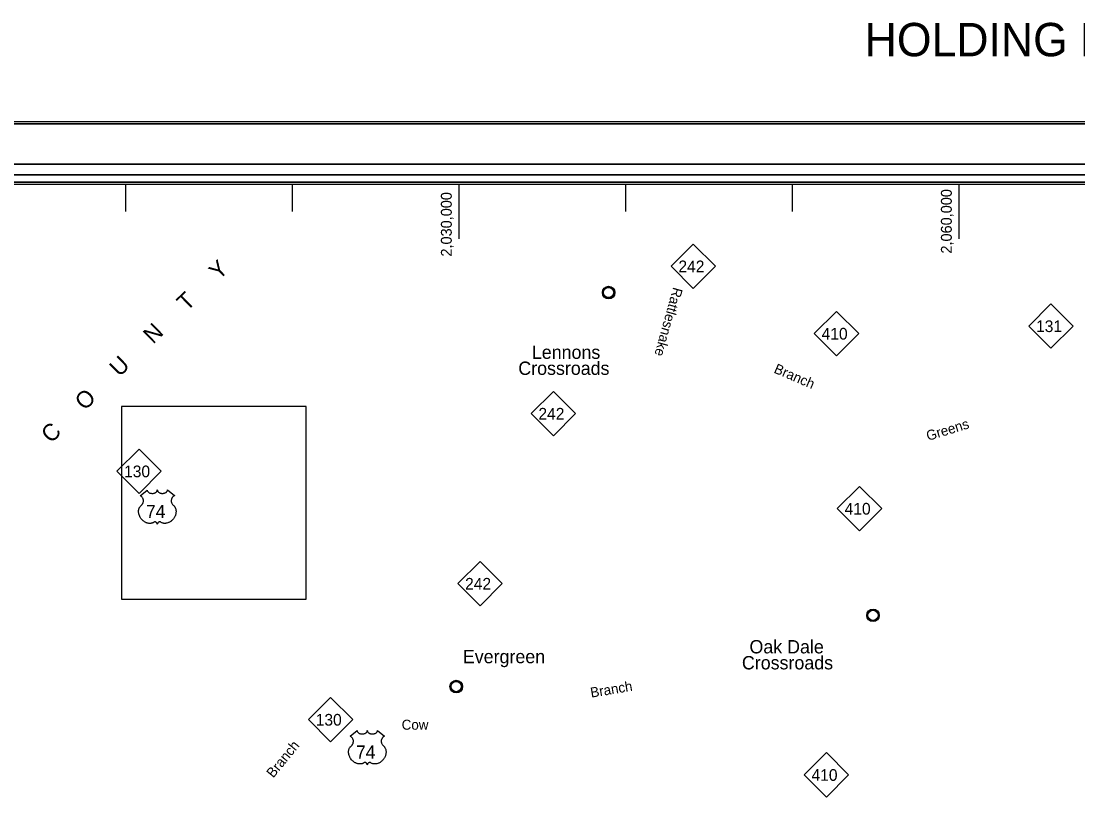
# Model space of a CAD drawing. Extents: x 5197761 to 5514561, y 1890130 to 2080942.
# Drawn here: x 5234499 to 5297901, y 2034063 to 2080942 of the extents above; entities that cross this region are included whole.
import ezdxf

# ---------------------------------------------------------------- set-up
doc = ezdxf.new("R2010")
doc.units = 0
for name, color, linetype in [('Exist Civil Demographics Community CELL', 7, 'Continuous'), ('Exist Civil Demographics Community Label', 7, 'Continuous'), ('Exist Hydrographic Creek Single Shore Label', 7, 'Continuous'), ('Exist Road Primary NC Shield CELL', 7, 'Continuous'), ('Exist Road Primary NC Shield Number Label', 7, 'Continuous'), ('Exist Road Primary US Shield CELL', 7, 'Continuous'), ('Exist Road Primary US Shield Number Label', 7, 'Continuous'), ('Map Preparation Base StatePlane Tick Label', 7, 'Continuous'), ('Map Preparation Base StatePlane Tick Mark', 7, 'Continuous'), ('Map Preparation Border Antique Large Shape', 7, 'Continuous'), ('Map Preparation Border Antique Small Shape', 7, 'Continuous'), ('Map Preparation Border Black Inside Shape', 7, 'Continuous'), ('Map Preparation Border Black Middle Shape', 7, 'Continuous'), ('Map Preparation Border Black Outside Shape', 7, 'Continuous'), ('Map Preparation County Outside Label', 7, 'Continuous'), ('Map Preparation Inset Cut Line', 7, 'Continuous'), ('Temp External Data Misc', 7, 'Continuous')]:
    doc.layers.add(name, color=color, linetype=linetype)

msp = doc.modelspace()

# ---------------------------------------------------------------- linework, layer by layer
at = {"layer": 'Exist Civil Demographics Community CELL'}
for points in [[(5269436, 2064714), (5269440, 2064737), (5269447, 2064763), (5269459, 2064792), (5269471, 2064815), (5269484, 2064838), (5269499, 2064858), (5269515, 2064876), (5269533, 2064894), (5269555, 2064912), (5269577, 2064927), (5269597, 2064938), (5269617, 2064948), (5269639, 2064957), (5269661, 2064965), (5269678, 2064969), (5269698, 2064972), (5269714, 2064975), (5269740, 2064976), (5269758, 2064976), (5269780, 2064975), (5269800, 2064972), (5269819, 2064968), (5269840, 2064962), (5269860, 2064954), (5269887, 2064943), (5269912, 2064929), (5269932, 2064915), (5269953, 2064899), (5269966, 2064886), (5269982, 2064869), (5269998, 2064850), (5270010, 2064831), (5270023, 2064811), (5270033, 2064791), (5270041, 2064771), (5270047, 2064751), (5270052, 2064732), (5270056, 2064708), (5270059, 2064689), (5270060, 2064665), (5270059, 2064642), (5270057, 2064619), (5270053, 2064597), (5270047, 2064573), (5270039, 2064549), (5270030, 2064529), (5270017, 2064505), (5270004, 2064484), (5269990, 2064465), (5269974, 2064446), (5269952, 2064426), (5269932, 2064410), (5269912, 2064396), (5269895, 2064386), (5269868, 2064373), (5269839, 2064362), (5269815, 2064356), (5269789, 2064351), (5269771, 2064349), (5269753, 2064348), (5269731, 2064348), (5269714, 2064350), (5269691, 2064353), (5269668, 2064358), (5269649, 2064363), (5269629, 2064371), (5269610, 2064379), (5269594, 2064388), (5269567, 2064404), (5269545, 2064421), (5269525, 2064439), (5269507, 2064458), (5269495, 2064474), (5269483, 2064491), (5269466, 2064519), (5269460, 2064534), (5269453, 2064550), (5269442, 2064582), (5269436, 2064611), (5269433, 2064631), (5269432, 2064656), (5269432, 2064675), (5269434, 2064701)], [(5285300, 2045357), (5285304, 2045380), (5285311, 2045406), (5285323, 2045435), (5285334, 2045458), (5285348, 2045481), (5285363, 2045501), (5285379, 2045519), (5285397, 2045537), (5285419, 2045555), (5285441, 2045570), (5285460, 2045581), (5285481, 2045591), (5285502, 2045600), (5285525, 2045608), (5285542, 2045612), (5285562, 2045615), (5285578, 2045618), (5285604, 2045619), (5285621, 2045619), (5285644, 2045618), (5285664, 2045615), (5285683, 2045611), (5285703, 2045605), (5285724, 2045597), (5285750, 2045586), (5285776, 2045572), (5285796, 2045558), (5285816, 2045542), (5285830, 2045529), (5285846, 2045511), (5285862, 2045493), (5285874, 2045474), (5285886, 2045454), (5285896, 2045434), (5285904, 2045414), (5285911, 2045394), (5285916, 2045375), (5285920, 2045351), (5285923, 2045332), (5285924, 2045308), (5285923, 2045285), (5285921, 2045262), (5285917, 2045240), (5285910, 2045216), (5285903, 2045192), (5285894, 2045172), (5285881, 2045148), (5285868, 2045127), (5285854, 2045108), (5285837, 2045089), (5285816, 2045069), (5285796, 2045053), (5285776, 2045039), (5285759, 2045029), (5285731, 2045016), (5285703, 2045005), (5285679, 2044999), (5285653, 2044994), (5285635, 2044992), (5285617, 2044991), (5285595, 2044991), (5285577, 2044993), (5285555, 2044996), (5285531, 2045001), (5285513, 2045006), (5285492, 2045014), (5285474, 2045022), (5285458, 2045031), (5285431, 2045047), (5285409, 2045064), (5285389, 2045082), (5285371, 2045101), (5285358, 2045117), (5285347, 2045134), (5285330, 2045162), (5285323, 2045176), (5285316, 2045193), (5285306, 2045225), (5285300, 2045254), (5285297, 2045274), (5285296, 2045299), (5285296, 2045318), (5285298, 2045344)], [(5260296, 2041084), (5260300, 2041106), (5260307, 2041133), (5260319, 2041162), (5260330, 2041185), (5260344, 2041207), (5260359, 2041228), (5260375, 2041245), (5260393, 2041264), (5260415, 2041282), (5260437, 2041297), (5260456, 2041308), (5260477, 2041318), (5260498, 2041327), (5260521, 2041335), (5260538, 2041339), (5260558, 2041342), (5260574, 2041345), (5260600, 2041346), (5260617, 2041346), (5260640, 2041345), (5260660, 2041342), (5260679, 2041338), (5260699, 2041332), (5260720, 2041324), (5260747, 2041313), (5260772, 2041299), (5260792, 2041284), (5260813, 2041268), (5260826, 2041256), (5260842, 2041238), (5260858, 2041220), (5260870, 2041201), (5260883, 2041181), (5260892, 2041161), (5260901, 2041140), (5260907, 2041120), (5260912, 2041102), (5260916, 2041078), (5260919, 2041059), (5260920, 2041035), (5260919, 2041012), (5260917, 2040989), (5260913, 2040967), (5260907, 2040943), (5260899, 2040919), (5260890, 2040899), (5260877, 2040875), (5260864, 2040854), (5260850, 2040835), (5260833, 2040816), (5260812, 2040796), (5260792, 2040780), (5260772, 2040766), (5260755, 2040756), (5260728, 2040743), (5260699, 2040732), (5260675, 2040726), (5260649, 2040721), (5260631, 2040719), (5260613, 2040718), (5260591, 2040718), (5260574, 2040720), (5260551, 2040723), (5260527, 2040728), (5260509, 2040733), (5260488, 2040741), (5260470, 2040749), (5260454, 2040757), (5260427, 2040774), (5260405, 2040791), (5260385, 2040809), (5260367, 2040828), (5260355, 2040844), (5260343, 2040861), (5260326, 2040889), (5260319, 2040903), (5260313, 2040919), (5260302, 2040952), (5260296, 2040980), (5260293, 2041001), (5260292, 2041026), (5260292, 2041045), (5260294, 2041071)]]:
    msp.add_lwpolyline(points, close=True, dxfattribs=at)
for centre, radius in [((5269747, 2064665), 377), ((5269746, 2064666), 307), ((5285610, 2045308), 377), ((5285609, 2045309), 307), ((5260607, 2041034), 377), ((5260605, 2041036), 307)]:
    msp.add_circle(centre, radius, dxfattribs=at)
at = {"layer": 'Exist Road Primary NC Shield CELL'}
for points in [[(5273497, 2066243), (5274829, 2067575), (5276161, 2066243), (5274829, 2064911)], [(5294955, 2062655), (5296287, 2063987), (5297619, 2062655), (5296287, 2061323)], [(5282089, 2062203), (5283421, 2063535), (5284753, 2062203), (5283421, 2060871)], [(5265098, 2057407), (5266430, 2058739), (5267762, 2057407), (5266430, 2056075)], [(5240239, 2053947), (5241571, 2055279), (5242903, 2053947), (5241571, 2052615)], [(5283469, 2051709), (5284801, 2053041), (5286133, 2051709), (5284801, 2050377)], [(5260699, 2047210), (5262031, 2048542), (5263363, 2047210), (5262031, 2045878)], [(5251736, 2039055), (5253068, 2040387), (5254400, 2039055), (5253068, 2037723)], [(5281483, 2035744), (5282815, 2037076), (5284147, 2035744), (5282815, 2034412)]]:
    msp.add_lwpolyline(points, close=True, dxfattribs=at)
at = {"layer": 'Exist Road Primary US Shield CELL'}
for points in [[(5242062, 2052824), (5242063, 2052806), (5242067, 2052785), (5242070, 2052774), (5242080, 2052754), (5242096, 2052730), (5242119, 2052706), (5242144, 2052685), (5242161, 2052674), (5242190, 2052658), (5242223, 2052644), (5242260, 2052634), (5242297, 2052626), (5242338, 2052622), (5242378, 2052621), (5242422, 2052624), (5242470, 2052634), (5242493, 2052639), (5242517, 2052648), (5242541, 2052657), (5242566, 2052671), (5242586, 2052684), (5242602, 2052696), (5242625, 2052717), (5242643, 2052740), (5242650, 2052752), (5242657, 2052764), (5242666, 2052790), (5242668, 2052801), (5242670, 2052825), (5242671, 2052805), (5242674, 2052793), (5242677, 2052781), (5242682, 2052768), (5242691, 2052750), (5242701, 2052735), (5242720, 2052712), (5242732, 2052701), (5242742, 2052692), (5242771, 2052672), (5242805, 2052655), (5242822, 2052648), (5242839, 2052642), (5242860, 2052636), (5242883, 2052630), (5242905, 2052627), (5242927, 2052623), (5242950, 2052621), (5242969, 2052621), (5242992, 2052621), (5243014, 2052623), (5243036, 2052625), (5243060, 2052629), (5243079, 2052633), (5243105, 2052640), (5243128, 2052648), (5243148, 2052657), (5243174, 2052671), (5243196, 2052684), (5243211, 2052697), (5243230, 2052714), (5243247, 2052734), (5243258, 2052749), (5243265, 2052764), (5243272, 2052781), (5243276, 2052798), (5243278, 2052812), (5243278, 2052825), (5243703, 2052486), (5243693, 2052483), (5243670, 2052471), (5243652, 2052460), (5243623, 2052440), (5243610, 2052429), (5243598, 2052417), (5243586, 2052404), (5243576, 2052392), (5243564, 2052375), (5243553, 2052358), (5243542, 2052339), (5243534, 2052323), (5243521, 2052289), (5243515, 2052267), (5243511, 2052249), (5243506, 2052211), (5243504, 2052193), (5243504, 2052175), (5243505, 2052156), (5243507, 2052138), (5243510, 2052119), (5243513, 2052103), (5243519, 2052082), (5243526, 2052059), (5243535, 2052036), (5243555, 2051999), (5243580, 2051961), (5243598, 2051940), (5243615, 2051922), (5243641, 2051900), (5243656, 2051887), (5243672, 2051871), (5243699, 2051840), (5243709, 2051826), (5243720, 2051809), (5243730, 2051793), (5243740, 2051774), (5243748, 2051759), (5243763, 2051722), (5243774, 2051687), (5243779, 2051668), (5243787, 2051627), (5243790, 2051606), (5243794, 2051565), (5243794, 2051516), (5243790, 2051469), (5243781, 2051415), (5243774, 2051382), (5243763, 2051344), (5243752, 2051311), (5243732, 2051263), (5243715, 2051228), (5243693, 2051186), (5243678, 2051162), (5243660, 2051135), (5243637, 2051104), (5243611, 2051072), (5243580, 2051037), (5243554, 2051012), (5243521, 2050982), (5243501, 2050966), (5243473, 2050944), (5243433, 2050918), (5243395, 2050896), (5243362, 2050879), (5243333, 2050866), (5243295, 2050852), (5243232, 2050834), (5243210, 2050830), (5243182, 2050826), (5243157, 2050823), (5243132, 2050822), (5243099, 2050822), (5243066, 2050824), (5243035, 2050829), (5243003, 2050835), (5242969, 2050846), (5242938, 2050858), (5242907, 2050873), (5242855, 2050906), (5242839, 2050914), (5242831, 2050916), (5242810, 2050917), (5242791, 2050913), (5242772, 2050906), (5242760, 2050899), (5242744, 2050889), (5242732, 2050879), (5242718, 2050866), (5242708, 2050854), (5242700, 2050845), (5242685, 2050822), (5242680, 2050811), (5242674, 2050796), (5242670, 2050775), (5242663, 2050802), (5242655, 2050819), (5242646, 2050834), (5242637, 2050848), (5242622, 2050865), (5242608, 2050878), (5242592, 2050891), (5242575, 2050901), (5242562, 2050908), (5242549, 2050913), (5242534, 2050917), (5242521, 2050918), (5242511, 2050917), (5242497, 2050914), (5242478, 2050900), (5242459, 2050888), (5242440, 2050875), (5242416, 2050863), (5242399, 2050855), (5242378, 2050847), (5242354, 2050839), (5242328, 2050832), (5242301, 2050827), (5242277, 2050823), (5242252, 2050821), (5242229, 2050820), (5242205, 2050820), (5242183, 2050822), (5242157, 2050824), (5242125, 2050829), (5242098, 2050835), (5242070, 2050843), (5242041, 2050852), (5242010, 2050863), (5241972, 2050880), (5241945, 2050894), (5241902, 2050918), (5241853, 2050953), (5241815, 2050983), (5241788, 2051008), (5241747, 2051049), (5241724, 2051076), (5241686, 2051124), (5241662, 2051159), (5241647, 2051185), (5241624, 2051226), (5241612, 2051252), (5241596, 2051290), (5241583, 2051324), (5241573, 2051357), (5241567, 2051378), (5241559, 2051414), (5241554, 2051440), (5241549, 2051475), (5241547, 2051513), (5241546, 2051547), (5241547, 2051576), (5241550, 2051609), (5241556, 2051645), (5241563, 2051675), (5241569, 2051697), (5241578, 2051723), (5241590, 2051753), (5241604, 2051781), (5241617, 2051804), (5241634, 2051829), (5241651, 2051851), (5241673, 2051874), (5241695, 2051896), (5241716, 2051913), (5241740, 2051937), (5241753, 2051952), (5241769, 2051972), (5241781, 2051991), (5241791, 2052008), (5241804, 2052032), (5241812, 2052051), (5241821, 2052080), (5241826, 2052100), (5241831, 2052126), (5241834, 2052150), (5241836, 2052180), (5241835, 2052206), (5241832, 2052235), (5241826, 2052263), (5241820, 2052288), (5241809, 2052316), (5241799, 2052336), (5241783, 2052364), (5241765, 2052390), (5241746, 2052411), (5241727, 2052430), (5241709, 2052444), (5241692, 2052456), (5241671, 2052470), (5241650, 2052480), (5241637, 2052485)], [(5254661, 2038398), (5254662, 2038380), (5254666, 2038359), (5254670, 2038348), (5254679, 2038328), (5254695, 2038303), (5254718, 2038280), (5254743, 2038259), (5254760, 2038248), (5254789, 2038232), (5254822, 2038218), (5254859, 2038208), (5254896, 2038200), (5254937, 2038196), (5254978, 2038195), (5255021, 2038198), (5255070, 2038207), (5255092, 2038213), (5255117, 2038222), (5255140, 2038231), (5255165, 2038245), (5255186, 2038258), (5255201, 2038269), (5255224, 2038291), (5255242, 2038313), (5255250, 2038326), (5255256, 2038338), (5255265, 2038364), (5255268, 2038375), (5255269, 2038399), (5255271, 2038379), (5255273, 2038366), (5255276, 2038354), (5255281, 2038342), (5255290, 2038323), (5255300, 2038308), (5255319, 2038286), (5255331, 2038275), (5255342, 2038266), (5255371, 2038246), (5255404, 2038229), (5255421, 2038222), (5255438, 2038216), (5255460, 2038209), (5255482, 2038204), (5255504, 2038200), (5255527, 2038197), (5255550, 2038195), (5255569, 2038195), (5255592, 2038195), (5255613, 2038196), (5255635, 2038199), (5255659, 2038203), (5255678, 2038207), (5255704, 2038214), (5255727, 2038222), (5255747, 2038231), (5255774, 2038245), (5255795, 2038258), (5255811, 2038271), (5255829, 2038288), (5255847, 2038308), (5255857, 2038323), (5255864, 2038338), (5255871, 2038354), (5255875, 2038371), (5255877, 2038386), (5255878, 2038399), (5256303, 2038060), (5256293, 2038056), (5256270, 2038045), (5256251, 2038034), (5256222, 2038014), (5256210, 2038002), (5256197, 2037991), (5256185, 2037978), (5256175, 2037966), (5256163, 2037949), (5256152, 2037932), (5256141, 2037913), (5256133, 2037897), (5256120, 2037863), (5256114, 2037841), (5256110, 2037823), (5256105, 2037785), (5256104, 2037767), (5256104, 2037749), (5256105, 2037730), (5256106, 2037712), (5256110, 2037693), (5256113, 2037677), (5256118, 2037656), (5256125, 2037633), (5256135, 2037610), (5256154, 2037573), (5256179, 2037535), (5256197, 2037514), (5256215, 2037496), (5256241, 2037474), (5256255, 2037461), (5256271, 2037445), (5256298, 2037414), (5256309, 2037400), (5256320, 2037383), (5256330, 2037366), (5256340, 2037348), (5256348, 2037333), (5256363, 2037296), (5256374, 2037261), (5256379, 2037242), (5256386, 2037200), (5256390, 2037180), (5256393, 2037139), (5256393, 2037090), (5256389, 2037043), (5256380, 2036989), (5256373, 2036956), (5256362, 2036918), (5256351, 2036885), (5256332, 2036837), (5256314, 2036801), (5256292, 2036760), (5256277, 2036735), (5256259, 2036709), (5256237, 2036678), (5256210, 2036646), (5256179, 2036611), (5256154, 2036586), (5256121, 2036556), (5256101, 2036539), (5256072, 2036518), (5256033, 2036492), (5255994, 2036469), (5255961, 2036453), (5255932, 2036440), (5255894, 2036426), (5255832, 2036408), (5255809, 2036404), (5255782, 2036400), (5255756, 2036397), (5255732, 2036396), (5255699, 2036396), (5255666, 2036398), (5255635, 2036403), (5255602, 2036409), (5255568, 2036419), (5255538, 2036431), (5255506, 2036447), (5255454, 2036480), (5255439, 2036488), (5255430, 2036490), (5255410, 2036491), (5255391, 2036487), (5255371, 2036479), (5255359, 2036473), (5255344, 2036463), (5255332, 2036453), (5255317, 2036440), (5255307, 2036428), (5255299, 2036419), (5255284, 2036396), (5255279, 2036385), (5255274, 2036370), (5255269, 2036349), (5255262, 2036376), (5255254, 2036393), (5255245, 2036408), (5255236, 2036422), (5255221, 2036439), (5255208, 2036452), (5255192, 2036465), (5255175, 2036475), (5255161, 2036482), (5255148, 2036487), (5255133, 2036491), (5255121, 2036492), (5255110, 2036491), (5255096, 2036488), (5255077, 2036474), (5255059, 2036462), (5255039, 2036449), (5255015, 2036437), (5254998, 2036429), (5254977, 2036421), (5254953, 2036413), (5254927, 2036406), (5254900, 2036401), (5254877, 2036397), (5254851, 2036395), (5254828, 2036394), (5254805, 2036394), (5254782, 2036396), (5254756, 2036398), (5254724, 2036403), (5254698, 2036409), (5254669, 2036416), (5254641, 2036425), (5254610, 2036437), (5254571, 2036454), (5254544, 2036468), (5254502, 2036492), (5254452, 2036527), (5254415, 2036557), (5254387, 2036582), (5254347, 2036623), (5254323, 2036650), (5254286, 2036698), (5254262, 2036733), (5254246, 2036759), (5254224, 2036800), (5254211, 2036826), (5254195, 2036864), (5254183, 2036898), (5254172, 2036931), (5254166, 2036951), (5254158, 2036988), (5254153, 2037014), (5254149, 2037049), (5254146, 2037087), (5254146, 2037121), (5254146, 2037150), (5254150, 2037183), (5254155, 2037218), (5254162, 2037249), (5254168, 2037271), (5254177, 2037297), (5254189, 2037327), (5254203, 2037355), (5254217, 2037378), (5254234, 2037403), (5254250, 2037425), (5254272, 2037448), (5254294, 2037470), (5254315, 2037487), (5254340, 2037511), (5254353, 2037525), (5254368, 2037546), (5254380, 2037565), (5254390, 2037581), (5254403, 2037606), (5254411, 2037625), (5254421, 2037654), (5254425, 2037674), (5254430, 2037700), (5254434, 2037724), (5254435, 2037754), (5254434, 2037779), (5254431, 2037809), (5254425, 2037837), (5254419, 2037862), (5254408, 2037890), (5254399, 2037910), (5254382, 2037938), (5254364, 2037964), (5254345, 2037985), (5254327, 2038004), (5254309, 2038018), (5254291, 2038030), (5254270, 2038043), (5254249, 2038054), (5254236, 2038059)]]:
    msp.add_lwpolyline(points, close=True, dxfattribs=at)
at = {"layer": 'Map Preparation Base StatePlane Tick Mark'}
for p, q in [((5240787, 2069519), (5240787, 2071145)), ((5250787, 2069519), (5250787, 2071145)), ((5260787, 2067894), (5260787, 2071145)), ((5270787, 2069519), (5270787, 2071145)), ((5280787, 2069519), (5280787, 2071145)), ((5290787, 2067894), (5290787, 2071145))]:
    msp.add_line(p, q, dxfattribs=at)
at = {"layer": 'Map Preparation Border Antique Large Shape'}
msp.add_lwpolyline([(5197907, 2074783), (5207205, 2074783), (5207205, 1892697), (5512539, 1892697), (5512539, 2072359), (5207205, 2072359), (5207205, 2074783), (5514414, 2074783), (5514414, 1890276), (5197907, 1890276)], close=True, dxfattribs=at)
at = {"layer": 'Map Preparation Border Antique Small Shape'}
msp.add_lwpolyline([(5207791, 2071720), (5208220, 2071720), (5208220, 1893712), (5511524, 1893712), (5511524, 2071291), (5208220, 2071291), (5208220, 2071720), (5207791, 2071720), (5511953, 2071720), (5511953, 1893283), (5208220, 1893283), (5207791, 1893283)], close=True, dxfattribs=at)
at = {"layer": 'Map Preparation Border Black Inside Shape'}
msp.add_lwpolyline([(5208220, 2071291), (5511524, 2071291), (5511524, 1893712), (5208366, 1893712), (5208366, 1893858), (5511378, 1893858), (5511378, 2071145), (5208366, 2071145), (5208366, 1893858), (5208366, 1893712), (5208220, 1893712), (5208220, 1893858)], close=True, dxfattribs=at)
at = {"layer": 'Map Preparation Border Black Middle Shape'}
msp.add_lwpolyline([(5207205, 2072359), (5512539, 2072359), (5512539, 1892697), (5511953, 1892697), (5207791, 1892697), (5207791, 1893283), (5511953, 1893283), (5511953, 2071720), (5207791, 2071720), (5207791, 1892697), (5207205, 1892697)], close=True, dxfattribs=at)
at = {"layer": 'Map Preparation Border Black Outside Shape'}
msp.add_lwpolyline([(5197761, 2074930), (5514561, 2074930), (5514561, 1890130), (5197907, 1890130), (5197907, 1890276), (5514414, 1890276), (5514414, 2074783), (5197907, 2074783), (5197907, 1890130), (5197761, 1890130)], close=True, dxfattribs=at)
at = {"layer": 'Map Preparation Inset Cut Line'}
msp.add_lwpolyline([(5251596, 2057829), (5240525, 2057829), (5240525, 2046279), (5251596, 2046279)], close=True, dxfattribs=at)

# ---------------------------------------------------------------- texts
at = {"layer": 'Exist Civil Demographics Community Label'}
for s, p in [('Lennons', (5265142, 2060687)), ('Crossroads', (5264329, 2059727)), ('Oak Dale', (5278198, 2043026)), ('Evergreen', (5261003, 2042436)), ('Crossroads', (5277744, 2042066))]:
    msp.add_text(s, height=800, dxfattribs=at).set_placement(p)
at = {"layer": 'Exist Hydrographic Creek Single Shore Label'}
for s, rotation, p in [('Rattlesnake', 254.46121, (5273626, 2065020)), ('Branch', 336.73791, (5279616, 2059875)), ('Greens', 17.14323, (5288913, 2055765)), ('Branch', 9.42427, (5268703, 2040370)), ('Cow', 0.05789, (5257332, 2038448)), ('Branch', 50.69659, (5249626, 2035520))]:
    msp.add_text(s, height=600, rotation=rotation, dxfattribs=at).set_placement(p)
at = {"layer": 'Exist Road Primary NC Shield Number Label'}
for s, p in [('242', (5273934, 2065884)), ('410', (5282525, 2061845)), ('131', (5295391, 2062296)), ('242', (5265534, 2057048)), ('130', (5240675, 2053589)), ('410', (5283905, 2051350)), ('242', (5261136, 2046851)), ('130', (5252172, 2038696)), ('410', (5281919, 2035385))]:
    msp.add_text(s, height=700, dxfattribs=at).set_placement(p)
at = {"layer": 'Exist Road Primary US Shield Number Label'}
for p in [(5241993, 2051149), (5254592, 2036723)]:
    msp.add_text('74', height=780, dxfattribs=at).set_placement(p)
at = {"layer": 'Map Preparation Base StatePlane Tick Label'}
for s, p in [('2,060,000', (5290335, 2067002)), ('2,030,000', (5260335, 2066823))]:
    msp.add_text(s, height=650, rotation=90, dxfattribs=at).set_placement(p)
at = {"layer": 'Map Preparation County Outside Label'}
msp.add_text('C     O     U     N     T     Y', height=1000, rotation=44.16519, dxfattribs=at).set_placement((5236289, 2055583))
at = {"layer": 'Temp External Data Misc'}
msp.add_text('HOLDING PBYP 701 and BUS 74/70 and NC 130 in Whiteville', height=2000, dxfattribs=at).set_placement((5285110, 2078835))

doc.saveas('drawing.dxf')
